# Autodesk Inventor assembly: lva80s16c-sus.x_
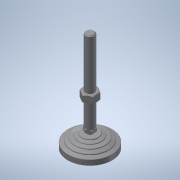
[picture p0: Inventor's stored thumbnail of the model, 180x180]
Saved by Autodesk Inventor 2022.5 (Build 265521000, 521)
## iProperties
Part Number: lva80s16c-sus.x_
Material: 一般
Document SubType Name: Assembly
Designer: ImaoCorp
Sending System: SOLIDWORKS 2017-2017317
MC: AMD64
MC_MODEL: Intel64 Family 6 Model 60 Stepping 3, GenuineIntel
OS: Windows_NT
FRU: Parasolid Version 29.0, build 201,  4-17-2017
FORMAT: text
GUISE: transmit
KEY: lva80s16c-sus
FILE: lva80s16c-sus.x_t
DATE: Mon Jul 01 18:10:08 2019
Author: ImaoCorp
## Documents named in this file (3)
- X:\14_SW2022-Inv2022\00_全2023-1023新製品(TCC)まで\l\lva80s16c-sus\LVA80S16C-SUS.iam
- X:\14_SW2022-Inv2022\00_全2023-1023新製品(TCC)まで\l\lva80s16c-sus\lva80s16c-sus_01.ipt
- X:\14_SW2022-Inv2022\00_全2023-1023新製品(TCC)まで\l\lva80s16c-sus\lva80s16c-sus_02.ipt
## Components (2 placed, 2 different names)
1. lva80s16c-sus_01
2. lva80s16c-sus_02
